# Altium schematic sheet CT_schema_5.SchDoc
size 277 x 170 mm
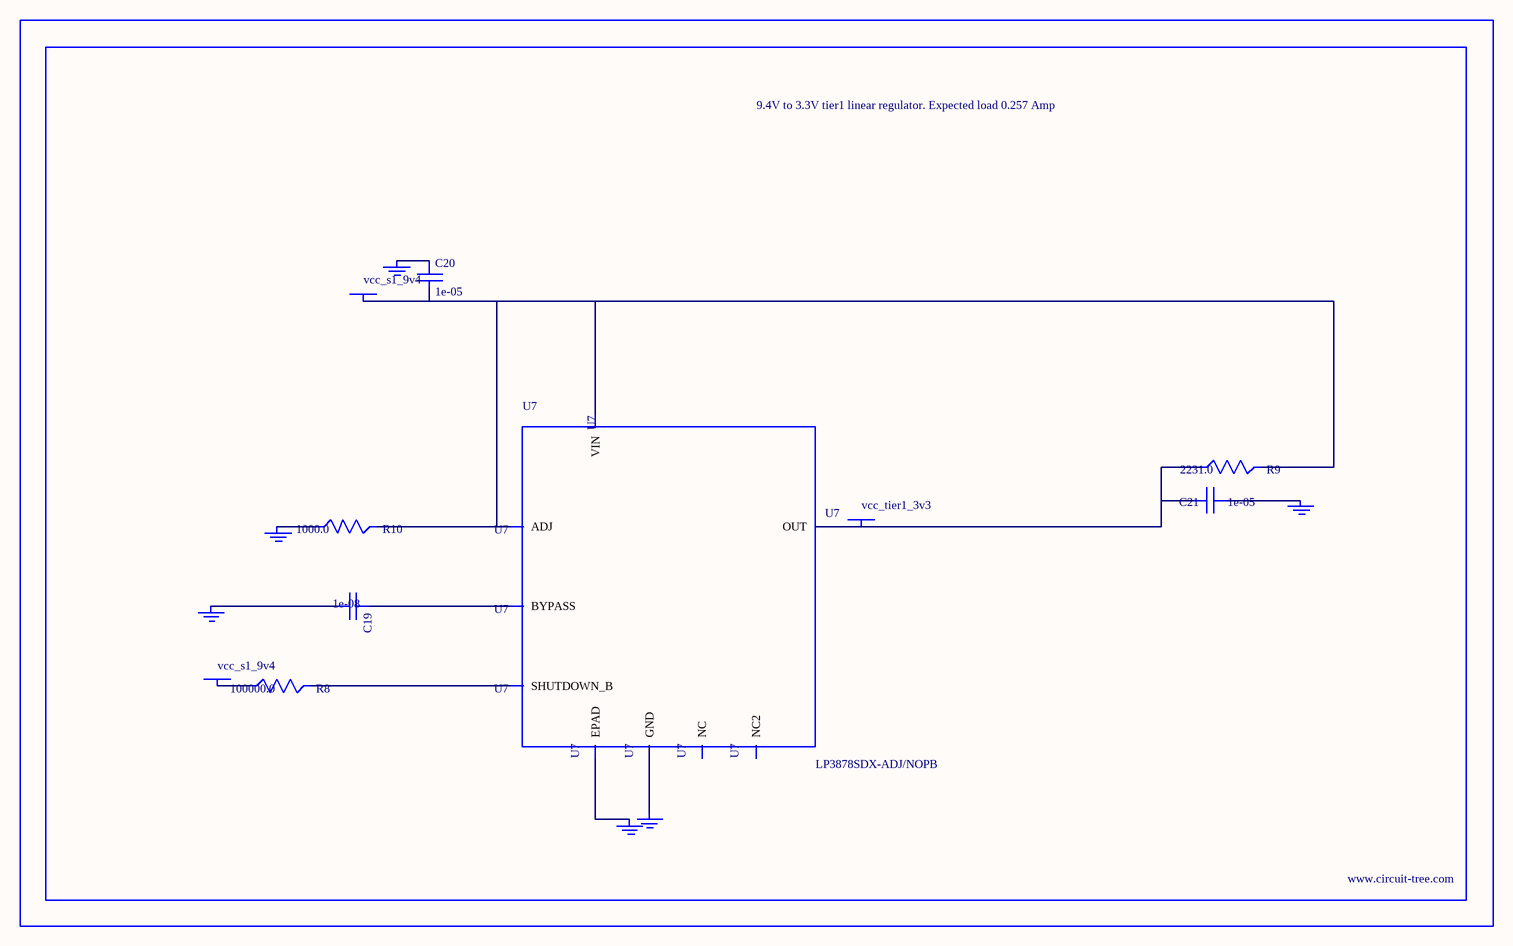
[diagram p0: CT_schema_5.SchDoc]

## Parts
BORDER4  (no value)
C19  1e-08  [C0402]
C20  1e-05  [C1206]
C21  1e-05  [C1210]
GND_INSTANCE_4_0  (no value)
GND_INSTANCE_4_1  (no value)
GND_INSTANCE_4_2  (no value)
GND_INSTANCE_4_3  (no value)
GND_INSTANCE_4_4  (no value)
GND_INSTANCE_4_5  (no value)
POWER_INSTANCE_4_0  vcc_s1_9v4
POWER_INSTANCE_4_1  vcc_s1_9v4
POWER_INSTANCE_4_2  vcc_tier1_3v3
R8  100000.0  [R0603]
R9  2231.0  [R0603]
R10  1000.0  [R0603]
U7  LP3878SDX-ADJ/NOPB  [WSON-8]

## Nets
NetC19_1: C19.1 U7.1(BYPASS)
NetC19_2: C19.2 GND_INSTANCE_4_0.0(GND)
NetC20_1: C20.1 GND_INSTANCE_4_1.0(GND)
NetC20_2: C20.2 POWER_INSTANCE_4_0.0(PWR) R9.2 R10.2 U7.4(VIN) U7.6(ADJ)
NetC21_1: C21.1 GND_INSTANCE_4_2.0(GND)
NetC21_2: C21.2 POWER_INSTANCE_4_2.0(PWR) R9.1 U7.5(OUT)
NetGND_INSTANCE_4_3_0: GND_INSTANCE_4_3.0(GND) R10.1
NetGND_INSTANCE_4_4_0: GND_INSTANCE_4_4.0(GND) U7.PAD(EPAD)
NetGND_INSTANCE_4_5_0: GND_INSTANCE_4_5.0(GND) U7.3(GND)
NetPOWER_INSTANCE_4_1_0: POWER_INSTANCE_4_1.0(PWR) R8.1
NetR8_2: R8.2 U7.8(SHUTDOWN_B)

Not connected (* = marked no-connect by the designer): U7 2(NC) 7(NC2)

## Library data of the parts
BORDER4 = BORDER_PAGE4
C19 = C0402C103K3RAC
C20 = C1206C106K3RACTU
C21 = GRM32DR61E106MA12L
GND_INSTANCE_4_0-GND_INSTANCE_4_5 = GND
POWER_INSTANCE_4_0-POWER_INSTANCE_4_2 = PWR
R8 = RC0603JR-07100KL
R9 = R9
R10 = RC0603JR-071KL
